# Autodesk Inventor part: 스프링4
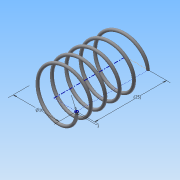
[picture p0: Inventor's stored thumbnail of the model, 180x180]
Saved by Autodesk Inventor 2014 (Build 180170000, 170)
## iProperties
Created: 2015-06
Part Number: 스프링4
Material: 강철, 연강
Document SubType Name: Modeling
Designer: Administrator
Density: 7.86 g/cm^3
Appearance: 강철
Mass: 1.53479 g
Surface Area: 7.89194 cm^2
Volume: 0.195266 cm^3
Author: Administrator
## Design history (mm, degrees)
sketch "스케치1"
  geometry: L1 (0, 0)-(8, 0); L2 (8, 0)-(8, 21.5); L3 (8, 21.5)-(0, 21.5); L4 (0, 21.5)-(0, 0); C1 r 0.5 at (8, 0)
  constraints: 8 end point, 2 parallel, 1 centre point, 1 coincident, 1 horizontal, 1 perpendicular
  dimensions: "d0" = 21.5 distance of L1.end L2.end (derived); "d1" = 16 diameter of L2 L4; "d2" = 1 diameter of C1
feature "코일1" sketch "스케치1" pitch "d3" = 10; turns "d5" = 5; dims "d4" = 21.5 (= d0), "d6" = 0, angle "d7" = 90 deg, angle "d8" = 90 deg, "d9" = 0, "d10" = 0
sketch "스케치2"
  geometry: L1 (-8.5, 0)-(-7.5, 0) reference; 1 further point
  constraints: 1 horizontal alignment
extrude "돌출1" cut sketch "스케치2" stored distance "d11" = 10; taper "d12" = 0 deg
node "작업 평면1"
sketch "스케치3"
  geometry: L1 (-7.5, 0)-(-8.5, 0) reference; 1 further point
  constraints: 1 horizontal alignment
extrude "돌출2" cut sketch "스케치3" stored distance "d14" = 10; taper "d15" = 0 deg
node "솔리드1"
node "절단 모서리 투영1"
node "절단 모서리 투영2"
other parameters: "d13" = 21.5 (= d0)
